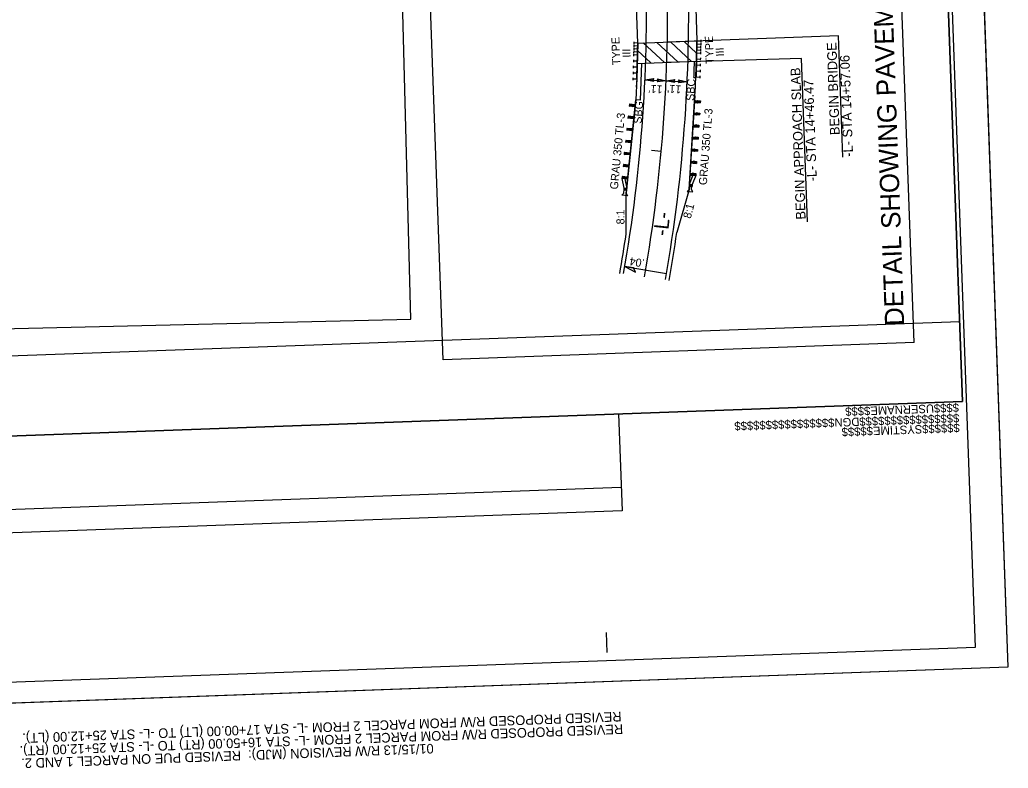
# Model space of a CAD drawing. Extents: x 2065068 to 2066582, y 144283 to 146300.
# Drawn here: x 2065965 to 2066582, y 144283 to 144750 of the extents above; entities that cross this region are included whole.
import ezdxf

# ---------------------------------------------------------------- set-up
doc = ezdxf.new("R2010")
doc.units = 0
for name, color, linetype in [('Prop Approach Slab', 7, 'Continuous'), ('Prop Approach Slab Hatching', 7, 'Continuous'), ('Prop Conc Shoulder Berm Gutter', 7, 'Continuous'), ('Prop Dimension', 7, 'Continuous'), ('Prop Dimension Text', 7, 'Continuous'), ('Prop EOT', 7, 'Continuous'), ('Prop Guardrail', 7, 'Continuous'), ('Prop Guardrail Anchor Unit CELL', 7, 'Continuous'), ('Prop Horizontal Alignment', 7, 'Continuous'), ('Prop Horizontal Alignment Station Label', 7, 'Continuous'), ('Prop Horizontal Alignment Tick Small', 7, 'Continuous'), ('Prop Paved Shoulder', 7, 'Continuous'), ('Prop Roadway Bridge', 7, 'Continuous'), ('Prop Structure Anchor Unit CELL', 7, 'Continuous'), ('Prop Superelevation  Arrow CELL', 7, 'Continuous'), ('Prop Superelevation Label', 7, 'Continuous'), ('Prop Terminator CELL', 7, 'Continuous'), ('Sheet Block Revision CELL', 7, 'Continuous'), ('Sheet Clip Boundary CELL', 7, 'Continuous'), ('Sheet Cutting Line CELL', 7, 'Continuous'), ('Sheet Layout Plan Border', 7, 'Continuous'), ('Sheet Plan CELL', 7, 'Continuous'), ('Sheet Plan Layout CELL', 7, 'Continuous'), ('Sheet Plot Border Inside CELL', 7, 'Continuous'), ('Sheet Plot Border Outside CELL', 7, 'Continuous')]:
    doc.layers.add(name, color=color, linetype=linetype)

# ---------------------------------------------------------------- blocks, each defined once
blk = doc.blocks.new('Super Arrow Terminator')
at = {"layer": 'Prop Superelevation  Arrow CELL'}
blk.add_lwpolyline([(0, 0), (-6, -2), (-4.625, 0)], close=True, dxfattribs=at)

msp = doc.modelspace()

# ---------------------------------------------------------------- linework, layer by layer
at = {"layer": 'Prop Approach Slab'}
msp.add_line((2066350.68, 144722.67), (2066387.68, 144724), dxfattribs=at)
for centre, radius, start, end in [((2065421.64, 144754.02), 929.57, 358.06725, 358.85044), ((2065421.61, 144754.02), 966.54, 358.22059, 358.97371)]:
    msp.add_arc(centre, radius, start, end, dxfattribs=at)
at = {"layer": 'Prop Approach Slab Hatching'}
for p, q in [((2066367.64, 144723.28), (2066354.51, 144735.5)), ((2066376.12, 144723.59), (2066362.99, 144735.8)), ((2066384.6, 144723.89), (2066371.47, 144736.11)), ((2066387.81, 144729.1), (2066379.95, 144736.41)), ((2066359.16, 144722.97), (2066350.89, 144730.66))]:
    msp.add_line(p, q, dxfattribs=at)
at = {"layer": 'Prop Conc Shoulder Berm Gutter'}
for p, q in [((2066352.72, 144699.69), (2066353.49, 144722.8)), ((2066386.11, 144713.85), (2066387.31, 144713.8)), ((2066352.72, 144699.69), (2066349.74, 144699.86))]:
    msp.add_line(p, q, dxfattribs=at)
msp.add_arc((2065421.64, 144754.02), 965.31, 357.61502, 358.22048, dxfattribs=at)
at = {"layer": 'Prop Dimension'}
for p, q in [((2066523.6, 144548.38), (2066506.68, 145016.55)), ((2066229.48, 144537.75), (2066212.56, 145005.92)), ((2066355.51, 144712.46), (2066381.89, 144711.28)), ((2066523.6, 144548.38), (2066229.48, 144537.75))]:
    msp.add_line(p, q, dxfattribs=at)
at = {"layer": 'Prop EOT'}
for radius, start in [(934.8, 349.99192), (961.2, 350.04596)]:
    msp.add_arc((2065421.64, 144754.02), radius, start, 2.07024, dxfattribs=at)
at = {"layer": 'Prop Guardrail'}
msp.add_line((2066350.37, 144713.34), (2066350.11, 144707.91), dxfattribs=at)
at = {"layer": 'Prop Guardrail Anchor Unit CELL'}
for p, q in [((2066386.77, 144702.51), (2066383.19, 144646.52)), ((2066349.74, 144699.86), (2066344.09, 144644.05)), ((2066345.85, 144697.19), (2066345.73, 144696)), ((2066345.73, 144696), (2066347.64, 144697.01)), ((2066349.31, 144695.63), (2066345.73, 144696)), ((2066349.43, 144696.83), (2066345.85, 144697.19)), ((2066347.52, 144695.82), (2066345.85, 144697.19)), ((2066347.64, 144697.01), (2066347.52, 144695.82)), ((2066347.52, 144695.82), (2066349.43, 144696.83)), ((2066349.31, 144695.63), (2066347.52, 144695.82)), ((2066347.64, 144697.01), (2066349.31, 144695.63)), ((2066349.43, 144696.83), (2066349.31, 144695.63)), ((2066386.58, 144699.47), (2066386.5, 144698.27)), ((2066388.38, 144699.35), (2066386.5, 144698.27)), ((2066386.5, 144698.27), (2066390.09, 144698.04)), ((2066386.5, 144698.27), (2066388.3, 144698.15)), ((2066386.58, 144699.47), (2066390.17, 144699.24)), ((2066388.3, 144698.15), (2066386.58, 144699.47)), ((2066388.38, 144699.35), (2066388.3, 144698.15)), ((2066388.3, 144698.15), (2066390.17, 144699.24)), ((2066390.09, 144698.04), (2066388.38, 144699.35)), ((2066390.17, 144699.24), (2066390.09, 144698.04)), ((2066345.03, 144689.67), (2066344.91, 144688.48)), ((2066344.91, 144688.48), (2066346.85, 144689.49)), ((2066348.55, 144688.11), (2066344.91, 144688.48)), ((2066348.67, 144689.31), (2066345.03, 144689.67)), ((2066346.73, 144688.29), (2066345.03, 144689.67)), ((2066346.85, 144689.49), (2066346.73, 144688.29)), ((2066348.67, 144689.31), (2066346.73, 144688.29)), ((2066346.85, 144689.49), (2066348.55, 144688.11)), ((2066387.92, 144691.8), (2066386.02, 144690.72)), ((2066386.02, 144690.72), (2066389.68, 144690.49)), ((2066386.1, 144691.92), (2066389.75, 144691.69)), ((2066386.1, 144691.92), (2066387.85, 144690.6)), ((2066387.92, 144691.8), (2066387.85, 144690.6)), ((2066387.85, 144690.6), (2066389.75, 144691.69)), ((2066389.68, 144690.49), (2066387.92, 144691.8)), ((2066389.75, 144691.69), (2066389.68, 144690.49)), ((2066344.27, 144682.15), (2066344.15, 144680.96)), ((2066347.91, 144681.78), (2066344.27, 144682.15)), ((2066345.97, 144680.77), (2066344.27, 144682.15)), ((2066387.44, 144684.26), (2066385.54, 144683.18)), ((2066385.54, 144683.18), (2066389.19, 144682.94)), ((2066385.61, 144684.37), (2066389.26, 144684.14)), ((2066385.61, 144684.37), (2066387.36, 144683.06)), ((2066387.44, 144684.26), (2066387.36, 144683.06)), ((2066387.36, 144683.06), (2066389.26, 144684.14)), ((2066389.19, 144682.94), (2066387.44, 144684.26)), ((2066389.26, 144684.14), (2066389.19, 144682.94)), ((2066344.15, 144680.96), (2066346.09, 144681.97)), ((2066347.79, 144680.59), (2066344.15, 144680.96)), ((2066346.09, 144681.97), (2066345.97, 144680.77)), ((2066347.91, 144681.78), (2066345.97, 144680.77)), ((2066346.09, 144681.97), (2066347.79, 144680.59)), ((2066385.13, 144676.83), (2066385.05, 144675.63)), ((2066386.95, 144676.71), (2066385.05, 144675.63)), ((2066385.13, 144676.83), (2066388.77, 144676.59)), ((2066385.13, 144676.83), (2066386.87, 144675.51)), ((2066386.95, 144676.71), (2066386.87, 144675.51)), ((2066386.87, 144675.51), (2066388.77, 144676.59)), ((2066388.69, 144675.4), (2066386.95, 144676.71)), ((2066388.77, 144676.59), (2066388.69, 144675.4)), ((2066343.53, 144674.63), (2066343.41, 144673.43)), ((2066343.41, 144673.43), (2066345.34, 144674.44)), ((2066347.03, 144673.06), (2066343.41, 144673.43)), ((2066347.15, 144674.26), (2066343.53, 144674.63)), ((2066345.22, 144673.25), (2066343.53, 144674.63)), ((2066345.34, 144674.44), (2066345.22, 144673.25)), ((2066347.15, 144674.26), (2066345.22, 144673.25)), ((2066345.34, 144674.44), (2066347.03, 144673.06)), ((2066347.15, 144674.26), (2066347.03, 144673.06)), ((2066385.05, 144675.63), (2066388.69, 144675.4)), ((2066342.64, 144667.12), (2066342.52, 144665.92)), ((2066342.52, 144665.92), (2066344.52, 144666.93)), ((2066346.27, 144665.54), (2066342.52, 144665.92)), ((2066346.39, 144666.74), (2066342.64, 144667.12)), ((2066344.4, 144665.73), (2066342.64, 144667.12)), ((2066344.52, 144666.93), (2066344.4, 144665.73)), ((2066346.39, 144666.74), (2066344.4, 144665.73)), ((2066344.52, 144666.93), (2066346.27, 144665.54)), ((2066386.53, 144669.16), (2066384.57, 144668.08)), ((2066384.57, 144668.08), (2066388.33, 144667.84)), ((2066384.65, 144669.28), (2066388.4, 144669.04)), ((2066384.65, 144669.28), (2066386.45, 144667.96)), ((2066386.53, 144669.16), (2066386.45, 144667.96)), ((2066386.45, 144667.96), (2066388.4, 144669.04)), ((2066388.33, 144667.84), (2066386.53, 144669.16)), ((2066388.4, 144669.04), (2066388.33, 144667.84)), ((2066342.05, 144659.58), (2066341.93, 144658.38)), ((2066341.93, 144658.38), (2066343.84, 144659.39)), ((2066345.51, 144658.02), (2066341.93, 144658.38)), ((2066345.63, 144659.21), (2066342.05, 144659.58)), ((2066343.72, 144658.2), (2066342.05, 144659.58)), ((2066343.84, 144659.39), (2066343.72, 144658.2)), ((2066345.63, 144659.21), (2066343.72, 144658.2)), ((2066343.84, 144659.39), (2066345.51, 144658.02)), ((2066385.96, 144661.62), (2066384.09, 144660.54)), ((2066384.09, 144660.54), (2066387.68, 144660.31)), ((2066384.16, 144661.74), (2066387.76, 144661.51)), ((2066384.16, 144661.74), (2066385.88, 144660.42)), ((2066385.96, 144661.62), (2066385.88, 144660.42)), ((2066385.88, 144660.42), (2066387.76, 144661.51)), ((2066387.68, 144660.31), (2066385.96, 144661.62)), ((2066387.76, 144661.51), (2066387.68, 144660.31)), ((2066341.21, 144652.06), (2066341.09, 144650.87)), ((2066341.09, 144650.87), (2066343.04, 144651.87)), ((2066344.87, 144651.69), (2066341.21, 144652.06)), ((2066342.92, 144650.68), (2066341.21, 144652.06)), ((2066343.04, 144651.87), (2066342.92, 144650.68)), ((2066344.87, 144651.69), (2066342.92, 144650.68)), ((2066343.04, 144651.87), (2066344.75, 144650.5)), ((2066385.44, 144652.87), (2066383.23, 144647.12)), ((2066385.52, 144654.07), (2066383.6, 144652.99)), ((2066383.6, 144652.99), (2066387.27, 144652.76)), ((2066383.68, 144654.19), (2066387.35, 144653.95)), ((2066383.68, 144654.19), (2066385.44, 144652.87)), ((2066387.27, 144652.76), (2066385.03, 144647.01)), ((2066385.52, 144654.07), (2066385.44, 144652.87)), ((2066385.44, 144652.87), (2066387.35, 144653.95)), ((2066387.27, 144652.76), (2066385.52, 144654.07)), ((2066387.35, 144653.95), (2066387.27, 144652.76)), ((2066344.75, 144650.5), (2066341.09, 144650.87)), ((2066341.09, 144650.87), (2066342.36, 144644.83)), ((2066342.92, 144650.68), (2066344.15, 144644.64)), ((2066383.28, 144646.48), (2066383.08, 144644.03)), ((2066383.15, 144645.92), (2066385.03, 144647.01)), ((2066383.15, 144645.92), (2066384.95, 144645.81)), ((2066383.23, 144647.12), (2066385.03, 144647.01)), ((2066384.95, 144645.81), (2066383.23, 144647.12)), ((2066384.01, 144646.42), (2066383.28, 144646.48)), ((2066384.74, 144646.36), (2066384.01, 144646.42)), ((2066384.54, 144643.91), (2066384.74, 144646.36)), ((2066385.03, 144647.01), (2066384.95, 144645.81)), ((2066385.03, 144647.01), (2066384.99, 144646.41)), ((2066341.19, 144640.37), (2066342.34, 144641.69)), ((2066344.71, 144640.08), (2066341.19, 144640.37)), ((2066342.36, 144644.83), (2066342.24, 144643.63)), ((2066342.24, 144643.63), (2066344.15, 144644.64)), ((2066344.03, 144643.45), (2066342.24, 144643.63)), ((2066342.36, 144644.83), (2066342.3, 144644.23)), ((2066342.34, 144641.69), (2066342.54, 144644.14)), ((2066344.15, 144644.64), (2066342.36, 144644.83)), ((2066344.03, 144643.45), (2066342.36, 144644.83)), ((2066342.54, 144644.14), (2066343.27, 144644.08)), ((2066343.27, 144644.08), (2066344, 144644.02)), ((2066344, 144644.02), (2066343.8, 144641.57)), ((2066343.8, 144641.57), (2066344.71, 144640.08)), ((2066383.08, 144644.03), (2066381.93, 144642.71)), ((2066381.93, 144642.71), (2066385.45, 144642.42)), ((2066385.45, 144642.42), (2066384.54, 144643.91))]:
    msp.add_line(p, q, dxfattribs=at)
at = {"layer": 'Prop Horizontal Alignment'}
msp.add_arc((2065421.64, 144754.02), 948, 350.00503, 2.07024, dxfattribs=at)
at = {"layer": 'Prop Horizontal Alignment Station Label'}
for p, q in [((2066476.36, 144739.94), (2066369.47, 144736.04)), ((2066479.1, 144664.06), (2066476.36, 144739.94)), ((2066453.36, 144725.76), (2066369.14, 144723.33)), ((2066457.05, 144623.8), (2066453.36, 144725.76))]:
    msp.add_line(p, q, dxfattribs=at)
at = {"layer": 'Prop Horizontal Alignment Tick Small'}
msp.add_line((2066365.7, 144667.69), (2066359.72, 144668.23), dxfattribs=at)
at = {"layer": 'Prop Paved Shoulder'}
for p, q in [((2066350.37, 144713.34), (2066350.68, 144722.67)), ((2066350.37, 144713.34), (2066349.74, 144699.86)), ((2066383.08, 144644.03), (2066386.77, 144702.51)), ((2066343.8, 144641.57), (2066349.74, 144699.86)), ((2066343.78, 144616.11), (2066343.8, 144641.57)), ((2066383.08, 144644.03), (2066375.46, 144617.08))]:
    msp.add_line(p, q, dxfattribs=at)
for radius, start, end in [(966.51, 356.94504, 358.22048), (932.4, 349.96036, 351.49425), (963.6, 350.02876, 351.82995)]:
    msp.add_arc((2065421.64, 144754.02), radius, start, end, dxfattribs=at)
at = {"layer": 'Prop Roadway Bridge'}
for p, q in [((2066351.02, 144735.37), (2066347.52, 144832.34)), ((2066384.49, 144833.67), (2066387.99, 144736.71)), ((2066351.02, 144735.37), (2066387.99, 144736.71))]:
    msp.add_line(p, q, dxfattribs=at)
at = {"layer": 'Prop Structure Anchor Unit CELL'}
for p, q in [((2066348.54, 144732.37), (2066348.5, 144731)), ((2066350.92, 144731.62), (2066348.52, 144731.69)), ((2066348.59, 144734.25), (2066348.55, 144732.87)), ((2066350.97, 144733.49), (2066348.57, 144733.56)), ((2066348.64, 144736.12), (2066348.6, 144734.75)), ((2066351.02, 144735.37), (2066348.62, 144735.43)), ((2066351.02, 144735.37), (2066350.42, 144712.88)), ((2066387.99, 144736.71), (2066387.45, 144714.21)), ((2066387.9, 144732.96), (2066390.3, 144732.9)), ((2066387.95, 144734.83), (2066390.35, 144734.77)), ((2066387.99, 144736.71), (2066390.39, 144736.65)), ((2066390.27, 144731.71), (2066390.24, 144730.34)), ((2066390.32, 144733.59), (2066390.28, 144732.21)), ((2066390.36, 144735.46), (2066390.33, 144734.09)), ((2066390.41, 144737.33), (2066390.38, 144735.96)), ((2066348.44, 144728.62), (2066348.4, 144727.25)), ((2066350.82, 144727.87), (2066348.42, 144727.94)), ((2066348.49, 144730.5), (2066348.45, 144729.12)), ((2066350.87, 144729.75), (2066348.47, 144729.81)), ((2066387.72, 144725.46), (2066390.12, 144725.4)), ((2066387.81, 144729.21), (2066390.21, 144729.15)), ((2066387.86, 144731.08), (2066390.26, 144731.02)), ((2066390.14, 144726.09), (2066390.1, 144724.71)), ((2066390.23, 144729.84), (2066390.19, 144728.46)), ((2066348.24, 144721.13), (2066348.2, 144719.75)), ((2066350.62, 144720.37), (2066348.22, 144720.44)), ((2066348.34, 144724.87), (2066348.3, 144723.5)), ((2066350.72, 144724.12), (2066348.32, 144724.19)), ((2066387.63, 144721.71), (2066390.03, 144721.65)), ((2066390.04, 144722.34), (2066390.01, 144720.96)), ((2066348.03, 144713.63), (2066348, 144712.25)), ((2066348.14, 144717.38), (2066348.1, 144716)), ((2066350.52, 144716.63), (2066348.12, 144716.69)), ((2066387.45, 144714.21), (2066389.84, 144714.15)), ((2066387.54, 144717.96), (2066389.94, 144717.9)), ((2066389.86, 144714.84), (2066389.83, 144713.47)), ((2066389.95, 144718.59), (2066389.92, 144717.22)), ((2066350.42, 144712.88), (2066348.02, 144712.94))]:
    msp.add_line(p, q, dxfattribs=at)
at = {"layer": 'Prop Superelevation  Arrow CELL'}
msp.add_line((2066342.98, 144595.98), (2066369, 144591.52), dxfattribs=at)
at = {"layer": 'Prop Terminator CELL'}
for points in [[(2066360.87, 144711.29), (2066355.51, 144712.46), (2066360.98, 144713.18), (2066360.25, 144712.25)], [(2066363.35, 144713.05), (2066368.7, 144711.87), (2066363.23, 144711.16), (2066363.96, 144712.09)], [(2066374.05, 144710.7), (2066368.7, 144711.87), (2066374.17, 144712.58), (2066373.43, 144711.65)], [(2066376.54, 144712.46), (2066381.89, 144711.28), (2066376.42, 144710.58), (2066377.15, 144711.5)]]:
    msp.add_lwpolyline(points, close=True, dxfattribs=at)
at = {"layer": 'Sheet Block Revision CELL'}
msp.add_line((2066340.72, 144457.89), (2065550.59, 144429.32), dxfattribs=at)
msp.add_lwpolyline([(2066341.27, 144443.35), (2065551.13, 144414.79), (2065548.92, 144475.29), (2066339.05, 144503.85)], close=True, dxfattribs=at)
at = {"layer": 'Sheet Clip Boundary CELL'}
msp.add_lwpolyline([(2066209.26, 144563.12), (2066197.36, 145017.22), (2066304.56, 145076.85), (2066276.35, 145857.16), (2065667.01, 145835.13), (2065670.41, 145741.24), (2065591.32, 145738.38), (2065521, 144770.65), (2065527.51, 144606.5), (2065634.3, 144549.42)], close=True, dxfattribs=at)
at = {"layer": 'Sheet Cutting Line CELL'}
for p, q in [((2066582.43, 144346.04), (2066521.61, 146028.44)), ((2065488.14, 144306.48), (2066582.43, 144346.04))]:
    msp.add_line(p, q, dxfattribs=at)
at = {"layer": 'Sheet Layout Plan Border'}
msp.add_lwpolyline([(2066552.11, 144561.57), (2066501.53, 145960.67), (2065663.57, 145930.38), (2065670.41, 145741.24), (2065459.06, 145733.6), (2065502.79, 144523.64)], close=True, dxfattribs=at)
at = {"layer": 'Sheet Plan CELL'}
for p, q in [((2066553.91, 144511.61), (2066553.91, 144511.61)), ((2066331.94, 144355.01), (2066331.5, 144367.5))]:
    msp.add_line(p, q, dxfattribs=at)
for points in [[(2065450.41, 145972.73), (2065504.6, 144473.67), (2066553.91, 144511.61), (2066499.73, 146010.64)], [(2066553.91, 144511.61), (2065504.63, 144473.65), (2065457.63, 145772.79), (2065607.59, 145778.22), (2065600.38, 145978.13), (2066499.73, 146010.64)]]:
    msp.add_lwpolyline(points, close=True, dxfattribs=at)
at = {"layer": 'Sheet Plan Layout CELL'}
msp.add_lwpolyline([(2065504.63, 144473.65), (2066553.91, 144511.61), (2066499.73, 146010.63), (2065661.76, 145980.34), (2065670.41, 145741.24), (2065459.06, 145733.6)], close=True, dxfattribs=at)
at = {"layer": 'Sheet Plot Border Inside CELL'}
msp.add_lwpolyline([(2066561.97, 144358.31), (2066501.77, 146023.21), (2065447.47, 145985.11), (2065507.66, 144320.2)], close=True, dxfattribs=at)
at = {"layer": 'Sheet Plot Border Outside CELL'}
msp.add_lwpolyline([(2066582.43, 144346.04), (2066521.61, 146028.44), (2065427.33, 145988.88), (2065488.14, 144306.48)], close=True, dxfattribs=at)

# ---------------------------------------------------------------- block references
at = {"layer": 'Prop Superelevation  Arrow CELL', "xscale": 1.1999976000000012, "yscale": -1.1999976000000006, "rotation": 170.26665880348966}
msp.add_blockref('Super Arrow Terminator', (2066342.98, 144595.98), dxfattribs=at)

# ---------------------------------------------------------------- texts
at = {"layer": 'Prop Dimension'}
msp.add_text('DETAIL SHOWING PAVEMENT AND BRIDGE RELATIONSHIP', height=12, rotation=92.07024, dxfattribs=at).set_placement((2066517.48, 144559.09))
at = {"layer": 'Prop Dimension Text'}
for s, rotation, p in [("11'", 176.22542, (2066366.59, 144708.85)), ("11'", 176.22542, (2066378.35, 144708.86)), ('SBC', 86.9583, (2066386.25, 144699.21)), ('SBG', 85.62156, (2066353.37, 144684.91)), ('8:1', 74.90803, (2066384.06, 144625.46)), ('8:1', 89.96588, (2066342.72, 144622.18))]:
    msp.add_text(s, height=5, rotation=rotation, dxfattribs=at).set_placement(p)
at = {"layer": 'Prop Guardrail Anchor Unit CELL'}
for rotation, p in [(84.60052, (2066338.6, 144643.86)), (85.56032, (2066394.12, 144646.56))]:
    msp.add_text('GRAU 350 TL-3', height=5, rotation=rotation, dxfattribs=at).set_placement(p)
at = {"layer": 'Prop Horizontal Alignment Station Label'}
for s, height, rotation, p in [('BEGIN BRIDGE', 6, 92.07024, (2066477.17, 144678.05)), ('-L- STA 14+57.06', 6, 92.07024, (2066485.53, 144664.52)), ('BEGIN APPROACH SLAB', 6, 92.07024, (2066455.89, 144625.3)), ('-L- STA 14+46.47', 6, 92.07024, (2066462.89, 144649.14)), ('-L-', 9.104, 83.99976, (2066369.78, 144614.63))]:
    msp.add_text(s, height=height, rotation=rotation, dxfattribs=at).set_placement(p)
at = {"layer": 'Prop Structure Anchor Unit CELL'}
for s, p in [('TYPE', (2066340.16, 144721.78)), ('TYPE', (2066398.5, 144722.5)), ('III', (2066404.89, 144727.13)), ('III', (2066346.56, 144726.41))]:
    msp.add_text(s, height=5, rotation=92.07024, dxfattribs=at).set_placement(p)
at = {"layer": 'Prop Superelevation Label'}
msp.add_text('.04', height=5, rotation=170.26666, dxfattribs=at).set_placement((2066355.61, 144600.16))
at = {"layer": 'Sheet Block Revision CELL'}
for s, p in [('                                                                REVISED PROPOSED R/W FROM PARCEL 2 FROM -L- STA 17+00.00 (LT) TO -L- STA 25+12.00 (LT). ', (2066483.37, 144323.13)), ('                                                                REVISED PROPOSED R/W FROM PARCEL 2 FROM -L- STA 16+50.00 (RT) TO -L- STA 25+12.00 (RT).', (2066484.36, 144315.3)), ('01/15/13 R/W REVISION (MJD):  REVISED PUE ON PARCEL 1 AND 2.', (2066223.43, 144298))]:
    msp.add_text(s, height=6, rotation=182.07024, dxfattribs=at).set_placement(p)
at = {"layer": 'Sheet Plan CELL'}
for s, p in [('$$$$USERNAME$$$$', (2066551.58, 144510.43)), ('$$$$$$$$$$$$$$$$DGN$$$$$$$$$$$$$$$$', (2066551.83, 144503.89)), ('$$$$$$SYSTIME$$$$$', (2066552.07, 144497.82))]:
    msp.add_text(s, height=5.25, rotation=182.07025, dxfattribs=at).set_placement(p)

doc.saveas('drawing.dxf')
